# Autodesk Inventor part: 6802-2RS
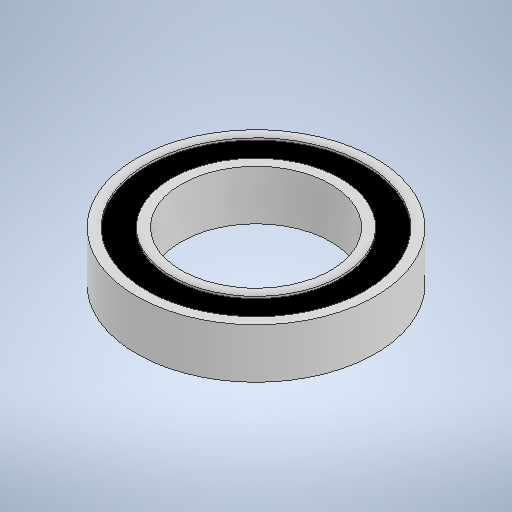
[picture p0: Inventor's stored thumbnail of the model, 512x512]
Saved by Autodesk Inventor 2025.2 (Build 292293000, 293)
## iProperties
Created: 2025-06
Part Number: 6802-2RS
Material: Generico
Document SubType Name: Modeling
Designer: R5800u
Density: 1 g/cm^3
Appearance: Default
Author: R5800u
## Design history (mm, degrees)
sketch "Schizzo1"
  geometry: C1 r 7.5 at (0, 0); C2 r 12 at (0, 0); 1 further point
  constraints: 2 centre point, 2 coincident
  dimensions: "d0" = 15 diameter of C1; "d1" = 24 diameter of C2
extrude "Estrusione1" new body sketch "Schizzo1" stored distance "d2" = 5; taper "d3" = 0 deg
sketch "Schizzo2"
  geometry: C1 r 8.5 at (0, 0); C2 r 11 at (0, 0); 1 further point
  constraints: 2 centre point, 2 coincident
  dimensions: "d4" = 17 diameter of C1; "d5" = 22 diameter of C2
extrude "Estrusione2" cut sketch "Schizzo2" distance "d6" = 0.2; taper "d7" = 0 deg
mirror "Speculare1"
node "Solido1"
